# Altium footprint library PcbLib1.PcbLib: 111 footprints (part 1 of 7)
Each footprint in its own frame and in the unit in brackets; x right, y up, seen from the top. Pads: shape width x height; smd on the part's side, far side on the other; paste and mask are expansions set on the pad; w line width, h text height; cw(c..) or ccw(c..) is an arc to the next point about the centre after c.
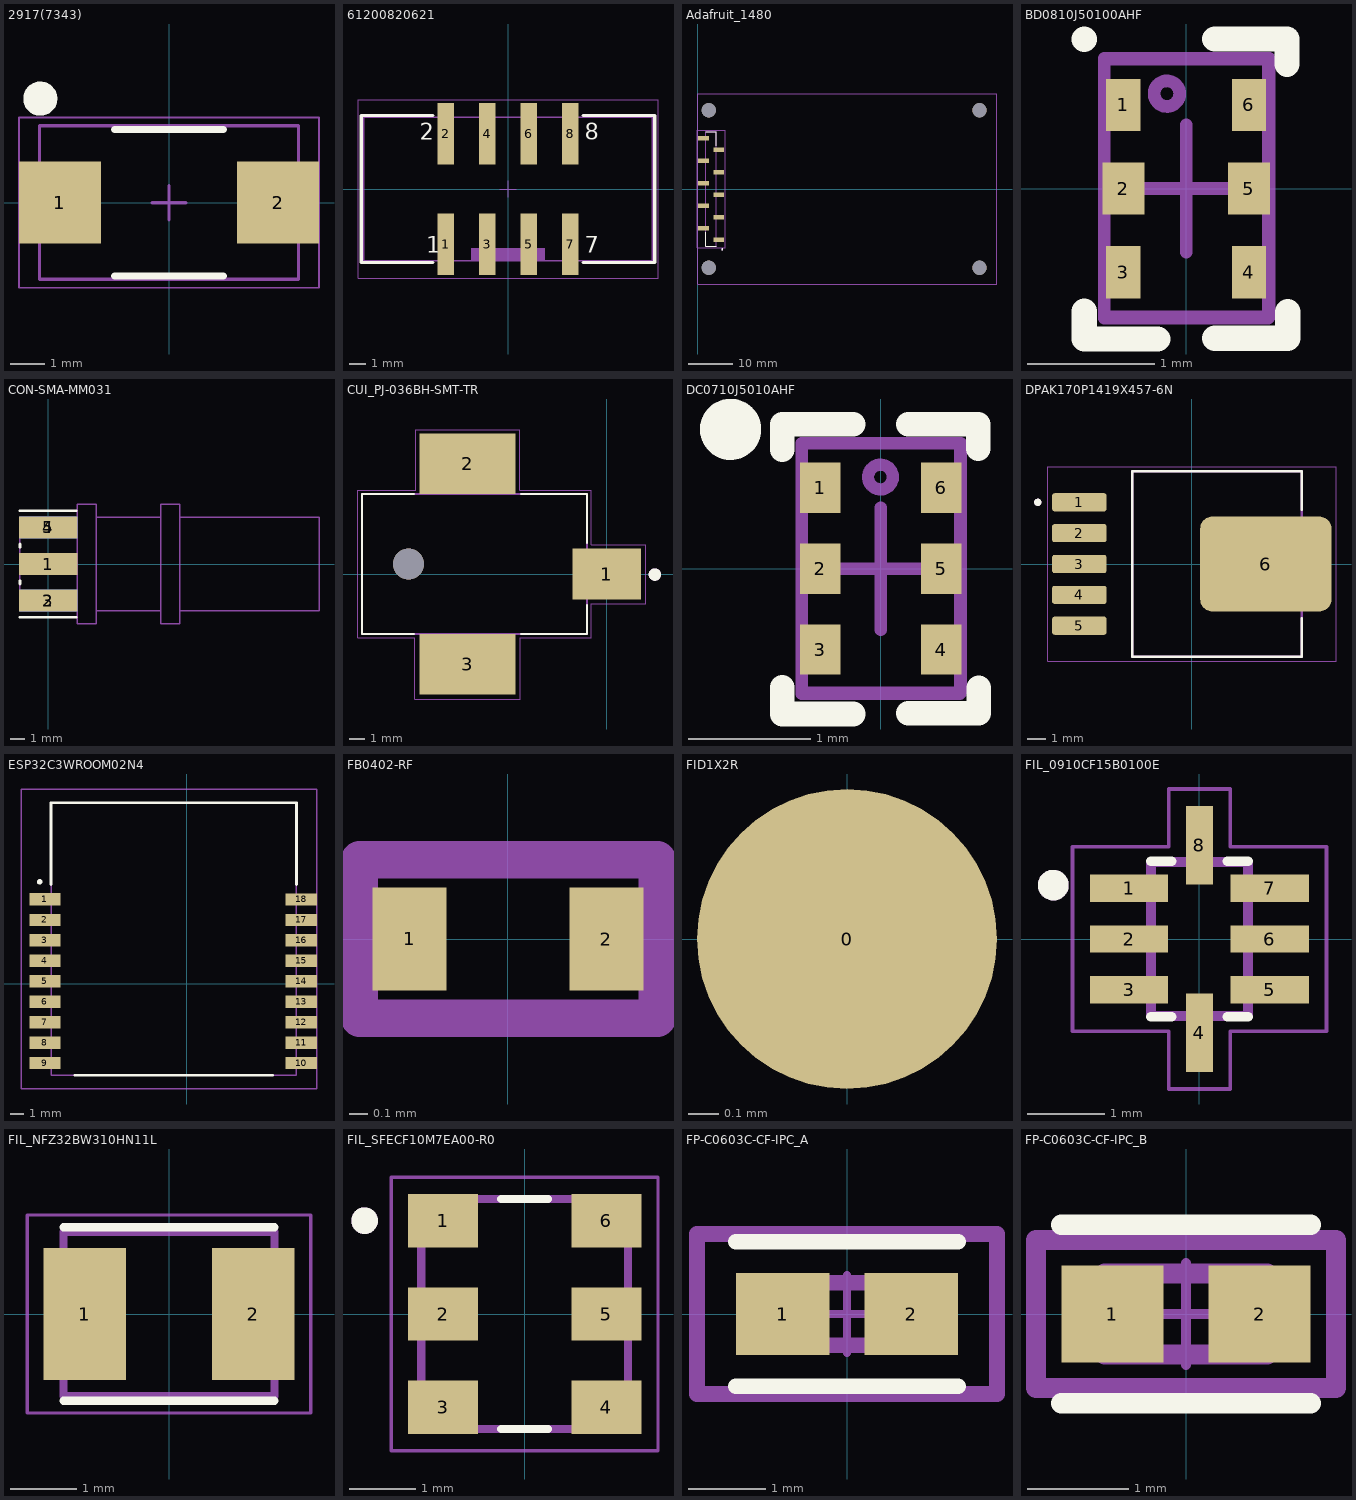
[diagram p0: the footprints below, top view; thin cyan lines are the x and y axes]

## 2917(7343) [mm] "Chip Capacitor, 2-Leads, Body 7,30x4,30mm, IPC Medium Density"
height 1.9
pads (2):
  rect 2.4x2.4 smd: 1(-3.2,0) 2(3.2,0)
Top Overlay:
  circle w0.5: c-3.775,3.05 r0.25
  lines w0.2: -1.6,-2.15 1.6,-2.15 ; -1.6,2.15 1.6,2.15
Mechanical 13:
  lines w0.1: -3.8,-2.25 3.8,-2.25 3.8,2.25 -3.8,2.25 -3.8,-2.25
Mechanical 15:
  lines w0.05: -4.4,-2.5 4.4,-2.5 4.4,2.5 -4.4,2.5 -4.4,-2.5
  lines w0.1: -0.5,0 0.5,0 ; 0,-0.5 0,0.5
3D body: height 1.9, standoff 0, extent -3.798,-2.25 3.807,2.25
3D body: height 0.85, standoff 0, extent 2.5,-1.205 3.851,1.196
3D body: height 0.85, standoff 0, extent -3.861,-1.205 -2.5,1.205
3D body: height 1.91, standoff 0, extent -3.409,-2.206 -2.938,2.207

## 61200820621 [mm] "8 pins, SMT, straight, gold plating"
height 9.2
pads (8):
  rect 1x3.75 smd: 1(-3.81,-3.375) 2(-3.81,3.375) 3(-1.27,-3.375) 4(-1.27,3.375) 5(1.27,-3.375) 6(1.27,3.375) 7(3.81,-3.375) 8(3.81,3.375)
Top Overlay:
  lines w0.2: -4.6,-4.5 -8.98,-4.5 -8.98,4.5 -4.6,4.5 ; 4.6,-4.5 8.98,-4.5 8.98,4.5 4.6,4.5
  text "7" at 4.7,-3.9 h1.02
  text "2" at -5.4,3 h1.02
  text "1" at -5,-3.9 h1.02
  text "8" at 4.7,3 h1.02
Mechanical 13:
  rectangle: -2.25,-4.4 2.25,-3.6
  lines w0.1: -8.83,-4.4 -8.83,4.4 8.83,4.4 8.83,-4.4 -8.83,-4.4
Mechanical 15:
  lines w0.05: -0.5,0 0.5,0 ; 0,-0.5 0,0.5 ; -9.18,-5.45 9.18,-5.45 9.18,5.45 -9.18,5.45 -9.18,-5.45
3D body "61200820621.stp": height 10.2, standoff 0.01, extent -8.89,-4.75 8.89,4.75

## Adafruit_1480 [mm] "SPI LCD MODULE 2.2\" 320x240p"
pads (14):
  rect 2.41x1.02 smd: 1(4.764,-11.431) 2(1.334,-8.891) 3(4.764,-6.351) 4(1.334,-3.811) 5(4.764,-1.271) 6(1.334,1.269) 7(4.764,3.809) 8(1.334,6.349) 9(4.764,8.889) 10(1.334,11.429)
  round 3.2 hole 3.2 unplated: ""(2.54,-17.75) ""(2.54,17.75) ""(63.56,-17.75) ""(63.56,17.755)
Top Overlay:
  circle w0.2: c5.589,-13.581 r0.1
  lines w0.2: 1.844,-9.751 1.844,-12.956 4.254,-12.956 ; 1.844,12.954 4.254,12.954 4.254,9.749
Mechanical 13:
  circle w0.2: c5.589,-13.581 r0.1
  lines w0.1: 1.844,-12.956 4.254,-12.956 4.254,12.954 1.844,12.954 1.844,-12.956
  lines w0.254: 0,-21.5 67.5,-21.5 67.5,21.5 0,21.5 0,0 0,-21.5
Mechanical 15:
  lines w0.05: -0.121,-13.206 6.219,-13.206 6.219,13.204 -0.121,13.204 -0.121,-13.206
3D body "SSW-110-22-F-S-VS.stp": height 9.76, standoff -0.02, extent 0.402,-13.004 5.558,12.904
3D body: height 14, standoff 10.7, extent 7.08,-20.47 61.08,20.53
3D body: height 10.7, standoff 9.7, extent 0.54,-20.39 66.94,20.41

## BD0810J50100AHF [mm] "RF Balun 800MHz ~ 1GHz 50 / 100 Ohm 0805"
height 0.84
pads (6):
  rect 0.27x0.41 smd mask+0.04: 1(-0.495,0.66) 3(-0.495,-0.66) 4(0.495,-0.66) 6(0.495,0.66)
  rect 0.33x0.41 smd mask+0.04: 2(-0.495,0) 5(0.495,0)
Top Overlay:
  lines w0.2: -0.803,-0.968 -0.803,-1.186 -0.225,-1.186 ; -0.803,1.175 -0.803,1.179 ; 0.225,-1.181 0.8,-1.181 0.8,-0.973 ; 0.225,1.179 0.795,1.179 0.795,0.98
Mechanical 13:
  circle w0.1: c-0.152,0.748 r0.101
  lines w0.1: -0.645,-1.024 0.648,-1.024 0.648,1.021 -0.645,1.021 -0.645,-1.024
Mechanical 15:
  lines w0.1: -0.5,0 0.5,0 ; 0,-0.5 0,0.5 ; -0.645,-1.013 0.653,-1.013 0.653,1.026 -0.645,1.026 -0.645,-1.013
3D body: height 0.85, standoff 0, extent -0.65,-1.029 0.653,1.031
3D body: height 0.86, standoff 0, extent -0.202,0.628 0.198,1.028

## CON-SMA-MM031 [mil] "Connector, SMA Female Edge Multi-Mount for 0.031\" Thick Board, 5-Lead, Body Dia. 7.9mm"
height 186.61
pads (5):
  rect 160x60 smd: 1(0,0) 2(0,-100) 5(0,100)
  rect 160x60 smd far side: 3(0,-100) 4(0,100)
Top Overlay:
  lines w7.87: -77.48,-145.75 76.06,-145.75 ; -77.48,-54.25 -77.48,-45.75 ; -77.48,45.75 -77.48,54.25 ; -77.48,145.75 76.06,145.75
Bottom Overlay:
  lines w7.87: -77.48,-145.75 76.06,-145.75 ; -77.48,-54.25 -77.48,-45.75 ; -77.48,45.75 -77.48,54.25 ; -77.48,145.75 76.06,145.75
Mechanical 13:
  lines w3.94: 80,-127.95 -77.48,-127.95 -77.48,127.95 80,127.95 ; 131.18,-127.95 308.35,-127.95 ; 131.18,127.95 308.35,127.95 ; 359.53,-127.95 741.42,-127.95 741.42,127.95 359.53,127.95 ; 80,-163.39 80,163.39 131.18,163.39 131.18,-163.39 80,-163.39 ; 308.35,-163.38 359.53,-163.38 359.53,163.39 308.35,163.39 308.35,-163.38
Mechanical 15:
  lines w3.94: -19.69,0 19.68,0 ; 0,-19.68 0,19.69
3D body: height 186.9, standoff -138.58, extent 80,-163.06 131.18,163.07
3D body: height 151.75, standoff -103.15, extent 359.53,-127.7 741.42,127.7
3D body: height 43.31, standoff 0, extent -77.46,-127.93 79.98,127.93
3D body: height 78.74, standoff 0, extent -77.46,-127.93 79.98,127.93
3D body: height 186.9, standoff -138.58, extent 308.35,-163.06 359.53,163.07
3D body: height 151.75, standoff -103.15, extent 131.18,-127.7 308.35,127.7

## CUI_PJ-036BH-SMT-TR [mm]
pads (4):
  rect 4.4x3.3 smd: 1(0,0)
  rect 6.2x3.9 smd: 2(-8.95,7.1) 3(-8.95,-5.8)
  round 2 hole 2 unplated: ""(-12.75,0.65)
Top Overlay:
  circle w0.4: c3.104,-0.03 r0.2
  lines w0.127: -12.4,-3.85 -15.75,-3.85 -15.75,5.15 -12.4,5.15 ; -5.5,-3.85 -1.25,-3.85 -1.25,-2 ; -5.5,5.15 -1.25,5.15 -1.25,2
Mechanical 13:
  circle w0.4: c3.104,-0.03 r0.2
  lines w0.127: -15.75,-3.85 -15.75,5.15 -1.25,5.15 -1.25,-3.85 -15.75,-3.85
Mechanical 15:
  lines w0.05: -16,-4.1 -16,5.4 -12.3,5.4 -12.3,9.3 -5.6,9.3 -5.6,5.4 -1,5.4 -1,1.9 2.5,1.9 2.5,-1.9 -1,-1.9 -1,-4.1 -5.55,-4.1 -5.55,-8.05 -12.35,-8.05 -12.35,-4.1 -16,-4.1
3D body "pj-036bh-smt-tr.stp": height 11.1, standoff -1.5, extent -15.875,-6.965 1.225,8.235

## DC0710J5010AHF [mm] "Directional Coupler"
height 0.84
pads (6):
  rect 0.33x0.41 smd mask+0.04: 1(-0.495,0.66) 2(-0.495,0) 3(-0.495,-0.66) 4(0.495,-0.66) 5(0.495,0) 6(0.495,0.66)
Top Overlay:
  circle w0.25: c-1.225,1.137 r0.125
  lines w0.2: -0.803,-0.968 -0.803,-1.186 -0.225,-1.186 ; -0.803,0.97 -0.803,1.179 -0.225,1.179 ; 0.225,-1.181 0.8,-1.181 0.8,-0.973 ; 0.225,1.179 0.795,1.179 0.795,0.98
Mechanical 13:
  circle w0.1: c-0.002,0.748 r0.101
  lines w0.1: -0.645,-1.024 0.648,-1.024 0.648,1.021 -0.645,1.021 -0.645,-1.024
Mechanical 15:
  lines w0.1: -0.5,0 0.5,0 ; 0,-0.5 0,0.5 ; -0.645,-1.013 0.653,-1.013 0.653,1.026 -0.645,1.026 -0.645,-1.013
3D body: height 0.85, standoff 0, extent -0.65,-1.029 0.653,1.031
3D body: height 0.86, standoff 0, extent -0.202,0.628 0.198,1.028

## DPAK170P1419X457-6N [mm]
pads (6):
  rrect25% 3x1 smd: 1(-6.21,3.404) 2(-6.21,1.702) 3(-6.21,0) 4(-6.21,-1.702) 5(-6.21,-3.404)
  rrect25% 7.24x5.25 smd paste-5: 6(4.08,0)
Top Overlay:
  circle w0.2: c-8.5,3.404 r0.1
  lines w0.127: 6.058,-3 6.058,-5.12 -3.282,-5.12 -3.282,5.12 6.058,5.12 6.058,3
Top Paste:
  region: 3.8,0.555 2.54,0.555 2.54,2.075 3.8,2.075
  region: 5.62,0.555 4.36,0.555 4.36,2.075 5.62,2.075
  region: 7.44,0.555 6.18,0.555 6.18,2.075 7.44,2.075
  region: 1.98,0.555 0.72,0.555 0.72,2.075 1.98,2.075
  region: 1.98,-2.075 0.72,-2.075 0.72,-0.555 1.98,-0.555
  region: 3.8,-2.075 2.54,-2.075 2.54,-0.555 3.8,-0.555
  region: 5.62,-2.075 4.36,-2.075 4.36,-0.555 5.62,-0.555
  region: 7.44,-2.075 6.18,-2.075 6.18,-0.555 7.44,-0.555
Mechanical 13:
  circle w0.2: c-8.5,3.404 r0.1
  lines w0.127: -3.282,-5.12 6.058,-5.12 6.058,5.12 -3.282,5.12 -3.282,-5.12
Mechanical 15:
  lines w0.05: -7.96,-5.37 7.95,-5.37 7.95,5.37 -7.96,5.37 -7.96,-5.37
3D body: height 1.4, standoff 0, extent 6.096,-5.207 7.366,5.207
3D body: height 4.57, standoff 0, extent -3.302,-5.207 6.142,5.207

## ESP32C3WROOM02N4 [mil]
pads (18):
  rect 90x35.43 smd: 1(-410,245) 2(-410,185.04) 3(-410,125.98) 4(-410,66.93) 5(-410,7.87) 6(-410,-51.18) 7(-410,-110.24) 8(-410,-169.29) 9(-410,-228.35) 10(330,-228.35) 11(330,-169.29) 12(330,-110.24) 13(330,-51.18) 14(330,7.87) 15(330,66.93) 16(330,125.98) 17(330,185.04) 18(330,244.09)
Top Overlay:
  lines w7.87: -428.94,295 ccw(c-425,295) -421.06,295 ; -428.94,295 cw(c-425,295) -421.06,295 ; -428.94,295 ccw(c-425,295) -421.06,295 ; -392.13,523.62 316.54,523.62 ; -392.13,523.62 316.54,523.62 ; -392.13,523.62 -392.13,287.4 -392.13,523.62 ; 316.54,523.62 316.54,287.4 316.54,523.62 ; -323.23,-263.78 247.64,-263.78 -323.23,-263.78
Mechanical 13:
  lines w3.94: -392.13,-263.78 316.54,-263.78 316.54,523.62 -392.13,523.62 -392.13,-263.78
Mechanical 15:
  lines w3.94: -478.74,-303.15 375.59,-303.15 375.59,562.99 -478.74,562.99 -478.74,-303.15
3D body "ESP32-C3-WROOM-02-N4.stp": height 125.98, standoff 0, extent -394.33,-268.7 314.33,518.7

## FB0402-RF [mil] "Ferrite Bead"
height 39.37
pads (2):
  rect 15.75x22 smd paste+0 mask+0: 1(-21,0) 2(21,0)
Mechanical 13:
  lines w8: -31.69,-16.93 -31.69,16.93 31.89,16.93 31.89,-16.93 -31.69,-16.93
3D body: height 12.2, standoff 0, extent -21.65,-10.83 -10.83,10.83
3D body: height 11.81, standoff 0, extent -21,-10.63 21,10.63
3D body: height 12.2, standoff 0, extent 10.83,-10.83 21.65,10.83

## FID1X2R [mm] "Fiducial - Round 1x2mm"
pads (1):
  round 1 smd paste-0.5 mask+0.5: 0(0,0)
Mechanical 19:
  text ".Designator" at -1.27,-0.127 h0.6

## FIL_0910CF15B0100E [mil]
pads (8):
  rect 40x14 smd: 1(-36,26) 2(-36,0) 3(-36,-26) 5(36,-26) 6(36,0) 7(36,26)
  rect 14x40 smd: 4(0,-48) 8(0,48)
Top Overlay:
  circle w7.87: c-74.8,27.56 r3.94
  lines w5: -24.8,-39.76 -14.17,-39.76 ; -24.8,39.76 -14.17,39.76 ; 14.17,-39.76 24.8,-39.76 ; 14.17,39.76 24.8,39.76
Mechanical 13:
  circle w7.87: c-74.8,27.56 r3.94
  lines w5: -24.8,-39.37 24.8,-39.37 24.8,39.37 -24.8,39.37 -24.8,-39.37
Mechanical 15:
  lines w1.97: -64.96,-47.24 -64.96,47.24 -15.75,47.24 -15.75,76.77 15.75,76.77 15.75,47.24 64.96,47.24 64.96,-47.24 15.75,-47.24 15.75,-76.77 -15.75,-76.77 -15.75,-47.24 -64.96,-47.24
3D body: height 27.56, standoff 0, extent -25.59,-39.37 25.59,39.37

## FIL_NFZ32BW310HN11L [mm]
pads (2):
  rect 1.25x2 smd: 1(-1.275,0) 2(1.275,0)
Top Overlay:
  lines w0.127: -1.6,-1.314 1.6,-1.314 ; -1.6,1.314 1.6,1.314
Mechanical 13:
  lines w0.127: -1.6,-1.25 1.6,-1.25 1.6,1.25 -1.6,1.25 -1.6,-1.25
Mechanical 15:
  lines w0.05: -2.15,-1.5 -2.15,1.5 2.15,1.5 2.15,-1.5 -2.15,-1.5
3D body "step_temp.STEP": height 1.7, standoff 0, extent -1.6,-1.25 1.6,1.25

## FIL_SFECF10M7EA00-R0 [mm]
pads (6):
  rect 1.05x0.8 smd mask+0: 1(-1.225,1.4) 2(-1.225,0) 3(-1.225,-1.4) 4(1.225,-1.4) 5(1.225,0) 6(1.225,1.4)
Top Overlay:
  circle w0.2: c-2.4,1.4 r0.1
  lines w0.127: -0.35,-1.725 0.35,-1.725 ; -0.35,1.725 0.35,1.725
Top Solder:
  region: 1.85,-1.9 0.6,-1.9 0.6,1.9 1.85,1.9
  region: -0.6,-1.9 -1.85,-1.9 -1.85,1.9 -0.6,1.9
Mechanical 13:
  circle w0.2: c-2.4,1.4 r0.1
  lines w0.127: -1.55,-1.725 -1.55,1.725 1.55,1.725 1.55,-1.725 -1.55,-1.725
Mechanical 15:
  lines w0.05: -2,-2.05 2,-2.05 2,2.05 -2,2.05 -2,-2.05
3D body "step_temp.STEP": height 1.4, standoff 0, extent -1.725,-1.55 1.725,1.55

## FP-C0603C-CF-IPC_A [mil]
pads (2):
  rect 47.5x41.66 smd paste+0 mask+0: 1(-32.51,0) 2(32.51,0)
Top Overlay:
  lines w7.87: -56.26,-36.58 56.26,-36.58 ; -56.26,36.58 56.26,36.58
Mechanical 5:
  lines w7.87: -75.95,-40.52 75.95,-40.52 75.95,40.52 -75.95,40.52 -75.95,-40.52
  text ".Designator" at 0,7.39 h39.37
Mechanical 13:
  lines w7.87: -31.5,-15.75 31.5,-15.75 31.5,15.75 -31.5,15.75 -31.5,-15.75
Mechanical 15:
  lines w7.87: -75.95,-40.52 75.95,-40.52 75.95,40.52 -75.95,40.52 -75.95,-40.52
Mechanical 16:
  lines w3.94: -19.68,0 19.68,0 ; 0,-19.68 0,19.68
3D body "Cap_KEMET_C0603C272M5JACTU_eec.STEP": height 10, standoff 0, extent -75.95,-40.52 75.95,40.52

## FP-C0603C-CF-IPC_B [mm]
pads (2):
  rect 1.007x0.958 smd paste+0 mask+0: 1(-0.726,0) 2(0.726,0)
Top Overlay:
  lines w0.2: -1.229,-0.879 1.229,-0.879 ; -1.229,0.879 1.229,0.879
Mechanical 5:
  lines w0.2: -1.479,-0.729 -1.479,0.729 1.479,0.729 1.479,-0.729 -1.479,-0.729
  text ".Designator" at 0,0.188 h1
Mechanical 13:
  lines w0.2: -0.8,-0.4 -0.8,0.4 0.8,0.4 0.8,-0.4 -0.8,-0.4
Mechanical 15:
  lines w0.2: -1.479,-0.729 -1.479,0.729 1.479,0.729 1.479,-0.729 -1.479,-0.729
Mechanical 16:
  lines w0.1: -0.5,0 0.5,0 ; 0,-0.5 0,0.5
3D body "Cap_KEMET_C0603C272M5JACTU_eec.STEP": height 0.25, standoff 0, extent -1.479,-0.729 1.479,0.729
